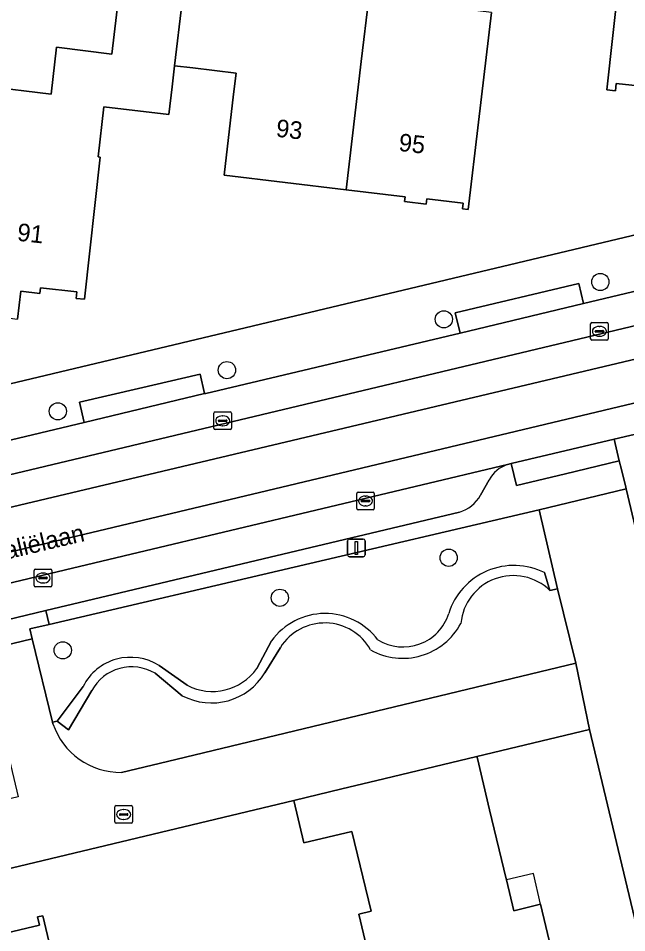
# Model space of a CAD drawing. Extents: x 162082 to 163401, y 388089 to 388636.
# Drawn here: x 163067.2 to 163101.7, y 388260.7 to 388312.7 of the extents above; entities that cross this region are included whole.
import ezdxf

# ---------------------------------------------------------------- set-up
doc = ezdxf.new("R2010")
doc.units = 0
for name, color, linetype in [('IMGEO_Boom', 7, 'Continuous'), ('IMGEO_Brandkraan', 7, 'Continuous'), ('IMGEO_Erf', 7, 'Continuous'), ('IMGEO_Fietspad_gesloten', 7, 'Continuous'), ('IMGEO_Groenvoorziening', 7, 'Continuous'), ('IMGEO_Haag', 7, 'Continuous'), ('IMGEO_Kolk', 7, 'Continuous'), ('IMGEO_Lichtmast', 7, 'Continuous'), ('IMGEO_Openbare_ruimte_label', 7, 'Continuous'), ('IMGEO_Pand', 7, 'Continuous'), ('IMGEO_Pand_nummerreeks', 7, 'Continuous'), ('IMGEO_Pand_overbouw', 7, 'Continuous'), ('IMGEO_Parkeervlak_gesloten', 7, 'Continuous'), ('IMGEO_Parkeervlak_open', 7, 'Continuous'), ('IMGEO_Rijbaan_lokaal_gesloten', 7, 'Continuous'), ('IMGEO_Voetpad_open', 7, 'Continuous')]:
    doc.layers.add(name, color=color, linetype=linetype)

msp = doc.modelspace()

# ---------------------------------------------------------------- linework, layer by layer
at = {"layer": 'IMGEO_Boom'}
for centre in [(163100.245, 388297.676), (163091.355, 388295.554), (163079.031, 388292.669), (163069.424, 388290.33), (163091.633, 388282.013), (163082.039, 388279.738), (163069.703, 388276.756)]:
    msp.add_circle(centre, 0.489, dxfattribs=at)
at = {"layer": 'IMGEO_Brandkraan'}
for p, q in [((163072.74, 388267.933), (163073.592, 388267.933)), ((163072.665, 388267.007), (163072.665, 388267.859)), ((163072.924, 388267.427), (163072.924, 388267.439)), ((163073.362, 388267.39), (163072.964, 388267.39)), ((163072.967, 388267.476), (163073.365, 388267.476)), ((163073.153, 388267.713), (163073.178, 388267.713)), ((163073.408, 388267.439), (163073.408, 388267.427)), ((163073.666, 388267.859), (163073.666, 388267.007)), ((163073.592, 388266.933), (163072.74, 388266.933)), ((163073.176, 388267.153), (163073.151, 388267.153))]:
    msp.add_line(p, q, dxfattribs=at)
for points in [[(163072.74, 388267.933), (163073.592, 388267.933)], [(163072.665, 388267.007), (163072.665, 388267.859)], [(163073.666, 388267.859), (163073.666, 388267.007)], [(163073.592, 388266.933), (163072.74, 388266.933)]]:
    msp.add_lwpolyline(points, dxfattribs=at)
for centre, radius, start, end in [((163072.742, 388267.857), 0.0765, 91.552, 178.448), ((163072.742, 388267.857), 0.0765, 91.552, 178.448), ((163073.59, 388267.857), 0.0765, 1.552, 88.448), ((163073.59, 388267.857), 0.0765, 1.552, 88.448), ((163072.964, 388267.436), 0.0403, 85.8775, 175.7526), ((163072.961, 388267.426), 0.0366, 178.938, 274.7102), ((163073.365, 388267.433), 0.043, 264.8664, 352.4533), ((163073.369, 388267.438), 0.0386, 1.7309, 96.639), ((163072.742, 388267.009), 0.0765, 181.552, 268.448), ((163072.742, 388267.009), 0.0765, 181.552, 268.448), ((163073.59, 388267.009), 0.0765, 271.552, 358.448), ((163073.59, 388267.009), 0.0765, 271.552, 358.448)]:
    msp.add_arc(centre, radius, start, end, dxfattribs=at)
for centre, major_axis, ratio, start_param, end_param in [((163073.152, 388267.433), (-0.387, 0.002), 0.722429, 4.712389, 7.853982), ((163073.177, 388267.433), (-0.39, 0.002), 0.717154, 1.570796, 4.712389)]:
    msp.add_ellipse(centre, major_axis=major_axis, ratio=ratio, start_param=start_param, end_param=end_param, dxfattribs=at)
at = {"layer": 'IMGEO_Erf'}
for points in [[(163013.441, 388370.076), (163002.97, 388276.7), (163142.597, 388309.979)], [(163115.606, 388318.173), (163114.904, 388310.765), (163115.585, 388310.468), (163115.233, 388307.247), (163114.536, 388307.323), (163114.509, 388307.074), (163114.127, 388307.119), (163114.177, 388307.482), (163111.934, 388307.715), (163111.899, 388307.38), (163110.705, 388307.504), (163110.765, 388307.946), (163107.613, 388308.272), (163101.145, 388308.941), (163101.103, 388308.536), (163100.622, 388308.594), (163101.28, 388314.604)], [(163065.297, 388308.795), (163069.042, 388308.351), (163069.356, 388311.006), (163072.487, 388310.619), (163073.322, 388317.664)], [(163094.057, 388312.987), (163093.32, 388306.76), (163092.732, 388301.794), (163092.421, 388301.831), (163092.46, 388302.161), (163090.397, 388302.405), (163090.36, 388302.097), (163089.126, 388302.243), (163089.158, 388302.514), (163085.798, 388302.912), (163078.866, 388303.733), (163079.413, 388308.351), (163079.555, 388309.542), (163077.085, 388309.835), (163076.059, 388309.956), (163075.918, 388308.765), (163075.731, 388307.184), (163072.033, 388307.622), (163071.721, 388304.785), (163071.83, 388304.772), (163070.94, 388296.69), (163070.468, 388296.746), (163070.51, 388297.107), (163068.444, 388297.351), (163068.405, 388297.018), (163067.313, 388297.148), (163067.132, 388295.572)], [(163104.946, 388250), (163099.632, 388272.251), (163093.238, 388270.721), (163093.262, 388270.617), (163093.959, 388267.699), (163094.894, 388263.781), (163094.91, 388263.713), (163095.326, 388261.968), (163096.857, 388262.333), (163097.97, 388257.667)], [(163087.681, 388256.901), (163086.52, 388261.764), (163087.221, 388261.933), (163086.135, 388266.466), (163083.409, 388265.815), (163082.833, 388268.229), (163042.708, 388258.625)], [(163062.455, 388259.741), (163068.38, 388261.15), (163068.27, 388261.61), (163068.57, 388261.682), (163069.727, 388256.818)]]:
    msp.add_lwpolyline(points, dxfattribs=at)
at = {"layer": 'IMGEO_Fietspad_gesloten'}
msp.add_lwpolyline([(163141.609, 388300.211), (163043.88, 388276.901), (163044.264, 388275.221), (163044.446, 388275.265), (163073.982, 388282.31), (163094.971, 388287.303), (163095.188, 388287.358), (163101.035, 388288.756), (163105.165, 388289.714), (163125.159, 388294.458), (163144.167, 388298.989)], dxfattribs=at)
at = {"layer": 'IMGEO_Groenvoorziening'}
for points in [[(163144.167, 388298.989), (163125.159, 388294.458), (163105.165, 388289.714), (163101.035, 388288.756), (163101.326, 388287.516), (163101.447, 388287.03), (163101.699, 388286.014), (163101.722, 388285.92), (163104.22, 388275.387), (163109.023, 388276.29), (163116.318, 388277.341), (163140.117, 388282.815), (163148.878, 388286.141), (163154.106, 388288.897), (163157.745, 388291.047), (163162.972, 388293.762)], [(163097.078, 388281.166), (163097.383, 388280.153), (163097.816, 388280.256), (163096.766, 388284.725), (163068.938, 388278.231), (163067.825, 388277.972), (163067.968, 388277.415), (163069.127, 388272.668), (163069.376, 388272.731), (163070.856, 388274.702)], [(163097.383, 388280.153), (163097.078, 388281.166)], [(163073.04, 388269.824), (163075.653, 388270.439), (163098.858, 388276.026), (163097.816, 388280.256)], [(163097.816, 388280.256), (163097.383, 388280.153)], [(163081.567, 388277.297), (163080.727, 388275.725)], [(163080.727, 388275.725), (163081.567, 388277.297)], [(163082.068, 388276.92), (163081.189, 388275.474)], [(163081.189, 388275.474), (163082.068, 388276.92)], [(163076.77, 388274.775), (163075.174, 388275.885)], [(163075.174, 388275.885), (163076.77, 388274.775)], [(163076.497, 388274.177), (163074.945, 388275.451)], [(163074.945, 388275.451), (163076.497, 388274.177)], [(163070.856, 388274.702), (163069.376, 388272.731), (163070.035, 388272.233), (163071.351, 388274.466)], [(163071.351, 388274.466), (163070.035, 388272.233), (163069.376, 388272.731), (163069.127, 388272.668), (163069.147, 388272.584)]]:
    msp.add_lwpolyline(points, dxfattribs=at)
for centre, radius, start, end in [((163095.342, 388277.695), 3.881, 63.4221, 162.8302), ((163095.342, 388277.695), 3.881, 63.4221, 162.8302), ((163095.3, 388278.007), 2.991, 45.8549, 174.6231), ((163095.3, 388278.007), 2.991, 45.8549, 174.6231), ((163084.608, 388275.087), 3.759, 36.9161, 143.9936), ((163084.608, 388275.087), 3.759, 36.9161, 143.9936), ((163089.036, 388279.673), 2.728, 238.5726, 342.2425), ((163089.036, 388279.673), 2.728, 238.5726, 342.2425), ((163084.588, 388275.328), 2.981, 29.097, 147.7058), ((163084.588, 388275.328), 2.981, 29.097, 147.7058), ((163089.016, 388280.051), 3.748, 240.8833, 331.92), ((163089.016, 388280.051), 3.748, 240.8833, 331.92), ((163073.549, 388273.344), 3.016, 57.3974, 153.2453), ((163073.549, 388273.344), 3.016, 57.3974, 153.2453), ((163073.616, 388273.251), 2.57, 58.8624, 151.7908), ((163073.616, 388273.251), 2.57, 58.8624, 151.7908), ((163078.208, 388277.5), 3.082, 242.1773, 324.823), ((163078.208, 388277.5), 3.082, 242.1773, 324.823), ((163078.153, 388277.321), 3.554, 242.2241, 328.6805), ((163078.153, 388277.321), 3.554, 242.2241, 328.6805), ((163072.986, 388273.874), 4.05, 198.5691, 270.7603)]:
    msp.add_arc(centre, radius, start, end, dxfattribs=at)
at = {"layer": 'IMGEO_Haag'}
for points in [[(163097.383, 388280.153), (163097.078, 388281.166)], [(163081.567, 388277.297), (163080.727, 388275.725)], [(163081.189, 388275.474), (163082.068, 388276.92)], [(163076.77, 388274.775), (163075.174, 388275.885)], [(163074.945, 388275.451), (163076.497, 388274.177)], [(163070.856, 388274.702), (163069.376, 388272.731), (163070.035, 388272.233), (163071.351, 388274.466)]]:
    msp.add_lwpolyline(points, dxfattribs=at)
for centre, radius, start, end in [((163095.342, 388277.695), 3.881, 63.4221, 162.8302), ((163095.3, 388278.007), 2.991, 45.8549, 174.6231), ((163084.608, 388275.087), 3.759, 36.9161, 143.9936), ((163089.036, 388279.673), 2.728, 238.5726, 342.2425), ((163084.588, 388275.328), 2.981, 29.097, 147.7058), ((163089.016, 388280.051), 3.748, 240.8833, 331.92), ((163073.549, 388273.344), 3.016, 57.3974, 153.2453), ((163073.616, 388273.251), 2.57, 58.8624, 151.7908), ((163078.208, 388277.5), 3.082, 242.1773, 324.823), ((163078.153, 388277.321), 3.554, 242.2241, 328.6805)]:
    msp.add_arc(centre, radius, start, end, dxfattribs=at)
at = {"layer": 'IMGEO_Kolk'}
for p, q in [((163099.697, 388294.449), (163099.697, 388295.301)), ((163099.772, 388295.375), (163100.624, 388295.375)), ((163099.999, 388294.918), (163100.397, 388294.918)), ((163100.185, 388295.155), (163100.21, 388295.155)), ((163100.698, 388295.301), (163100.698, 388294.449)), ((163099.956, 388294.869), (163099.956, 388294.881)), ((163100.394, 388294.832), (163099.996, 388294.832)), ((163100.208, 388294.595), (163100.183, 388294.595)), ((163100.44, 388294.881), (163100.44, 388294.869)), ((163100.624, 388294.375), (163099.772, 388294.375)), ((163078.367, 388290.293), (163079.219, 388290.293)), ((163078.292, 388289.367), (163078.292, 388290.219)), ((163078.551, 388289.787), (163078.551, 388289.799)), ((163078.989, 388289.75), (163078.591, 388289.75)), ((163078.594, 388289.836), (163078.992, 388289.836)), ((163078.78, 388290.073), (163078.805, 388290.073)), ((163079.035, 388289.799), (163079.035, 388289.787)), ((163079.293, 388290.219), (163079.293, 388289.367)), ((163079.219, 388289.293), (163078.367, 388289.293)), ((163078.803, 388289.513), (163078.778, 388289.513)), ((163086.404, 388284.808), (163086.404, 388285.66)), ((163086.479, 388285.734), (163087.331, 388285.734)), ((163087.405, 388285.66), (163087.405, 388284.808)), ((163086.663, 388285.228), (163086.663, 388285.24)), ((163087.101, 388285.191), (163086.703, 388285.191)), ((163086.706, 388285.277), (163087.104, 388285.277)), ((163086.892, 388285.514), (163086.917, 388285.514)), ((163087.147, 388285.24), (163087.147, 388285.228)), ((163087.331, 388284.734), (163086.479, 388284.734)), ((163086.915, 388284.954), (163086.89, 388284.954)), ((163068.081, 388280.433), (163068.081, 388281.285)), ((163068.156, 388281.359), (163069.008, 388281.359)), ((163068.383, 388280.902), (163068.781, 388280.902)), ((163068.569, 388281.139), (163068.594, 388281.139)), ((163069.082, 388281.285), (163069.082, 388280.433)), ((163069.008, 388280.359), (163068.156, 388280.359)), ((163068.34, 388280.853), (163068.34, 388280.865)), ((163068.778, 388280.816), (163068.38, 388280.816)), ((163068.592, 388280.579), (163068.567, 388280.579)), ((163068.824, 388280.865), (163068.824, 388280.853))]:
    msp.add_line(p, q, dxfattribs=at)
for points in [[(163099.697, 388294.449), (163099.697, 388295.301)], [(163099.772, 388295.375), (163100.624, 388295.375)], [(163100.698, 388295.301), (163100.698, 388294.449)], [(163100.624, 388294.375), (163099.772, 388294.375)], [(163078.367, 388290.293), (163079.219, 388290.293)], [(163078.292, 388289.367), (163078.292, 388290.219)], [(163079.293, 388290.219), (163079.293, 388289.367)], [(163079.219, 388289.293), (163078.367, 388289.293)], [(163086.404, 388284.808), (163086.404, 388285.66)], [(163086.479, 388285.734), (163087.331, 388285.734)], [(163087.405, 388285.66), (163087.405, 388284.808)], [(163087.331, 388284.734), (163086.479, 388284.734)], [(163068.081, 388280.433), (163068.081, 388281.285)], [(163068.156, 388281.359), (163069.008, 388281.359)], [(163069.082, 388281.285), (163069.082, 388280.433)], [(163069.008, 388280.359), (163068.156, 388280.359)]]:
    msp.add_lwpolyline(points, dxfattribs=at)
for centre, radius, start, end in [((163099.774, 388295.299), 0.0765, 91.552, 178.448), ((163099.774, 388295.299), 0.0765, 91.552, 178.448), ((163099.996, 388294.878), 0.0403, 85.8775, 175.7526), ((163100.401, 388294.88), 0.0386, 1.7309, 96.639), ((163100.622, 388295.299), 0.0765, 1.552, 88.448), ((163100.622, 388295.299), 0.0765, 1.552, 88.448), ((163099.774, 388294.451), 0.0765, 181.552, 268.448), ((163099.774, 388294.451), 0.0765, 181.552, 268.448), ((163099.993, 388294.868), 0.0366, 178.938, 274.7102), ((163100.397, 388294.875), 0.043, 264.8664, 352.4533), ((163100.622, 388294.451), 0.0765, 271.552, 358.448), ((163100.622, 388294.451), 0.0765, 271.552, 358.448), ((163078.369, 388290.217), 0.0765, 91.552, 178.448), ((163078.369, 388290.217), 0.0765, 91.552, 178.448), ((163079.217, 388290.217), 0.0765, 1.552, 88.448), ((163079.217, 388290.217), 0.0765, 1.552, 88.448), ((163078.591, 388289.796), 0.0403, 85.8775, 175.7526), ((163078.588, 388289.786), 0.0366, 178.938, 274.7102), ((163078.992, 388289.793), 0.043, 264.8664, 352.4533), ((163078.996, 388289.798), 0.0386, 1.7309, 96.639), ((163078.369, 388289.369), 0.0765, 181.552, 268.448), ((163078.369, 388289.369), 0.0765, 181.552, 268.448), ((163079.217, 388289.369), 0.0765, 271.552, 358.448), ((163079.217, 388289.369), 0.0765, 271.552, 358.448), ((163086.481, 388285.658), 0.0765, 91.552, 178.448), ((163086.481, 388285.658), 0.0765, 91.552, 178.448), ((163087.329, 388285.658), 0.0765, 1.552, 88.448), ((163087.329, 388285.658), 0.0765, 1.552, 88.448), ((163086.703, 388285.237), 0.0403, 85.8775, 175.7526), ((163086.7, 388285.227), 0.0366, 178.938, 274.7102), ((163087.104, 388285.234), 0.043, 264.8664, 352.4533), ((163087.108, 388285.239), 0.0386, 1.7309, 96.639), ((163086.481, 388284.81), 0.0765, 181.552, 268.448), ((163086.481, 388284.81), 0.0765, 181.552, 268.448), ((163087.329, 388284.81), 0.0765, 271.552, 358.448), ((163087.329, 388284.81), 0.0765, 271.552, 358.448), ((163068.158, 388281.283), 0.0765, 91.552, 178.448), ((163068.158, 388281.283), 0.0765, 91.552, 178.448), ((163068.38, 388280.862), 0.0403, 85.8775, 175.7526), ((163068.785, 388280.864), 0.0386, 1.7309, 96.639), ((163069.006, 388281.283), 0.0765, 1.552, 88.448), ((163069.006, 388281.283), 0.0765, 1.552, 88.448), ((163068.158, 388280.435), 0.0765, 181.552, 268.448), ((163068.158, 388280.435), 0.0765, 181.552, 268.448), ((163068.377, 388280.852), 0.0366, 178.938, 274.7102), ((163068.781, 388280.859), 0.043, 264.8664, 352.4533), ((163069.006, 388280.435), 0.0765, 271.552, 358.448), ((163069.006, 388280.435), 0.0765, 271.552, 358.448)]:
    msp.add_arc(centre, radius, start, end, dxfattribs=at)
for centre, major_axis, ratio, start_param, end_param in [((163100.184, 388294.875), (-0.387, 0.002), 0.722429, 4.712389, 7.853982), ((163100.209, 388294.875), (-0.39, 0.002), 0.717154, 1.570796, 4.712389), ((163078.779, 388289.793), (-0.387, 0.002), 0.722429, 4.712389, 7.853982), ((163078.804, 388289.793), (-0.39, 0.002), 0.717154, 1.570796, 4.712389), ((163086.891, 388285.234), (-0.387, 0.002), 0.722429, 4.712389, 7.853982), ((163086.916, 388285.234), (-0.39, 0.002), 0.717154, 1.570796, 4.712389), ((163068.568, 388280.859), (-0.387, 0.002), 0.722429, 4.712389, 7.853982), ((163068.593, 388280.859), (-0.39, 0.002), 0.717154, 1.570796, 4.712389)]:
    msp.add_ellipse(centre, major_axis=major_axis, ratio=ratio, start_param=start_param, end_param=end_param, dxfattribs=at)
at = {"layer": 'IMGEO_Lichtmast'}
for p, q in [((163085.888, 388282.17), (163085.888, 388282.97)), ((163085.888, 388282.97), (163085.888, 388282.17)), ((163085.988, 388283.07), (163086.778, 388283.07)), ((163086.778, 388283.07), (163085.988, 388283.07)), ((163086.878, 388282.97), (163086.878, 388282.17)), ((163086.878, 388282.17), (163086.878, 388282.97)), ((163086.778, 388282.07), (163085.988, 388282.07)), ((163085.988, 388282.07), (163086.778, 388282.07))]:
    msp.add_line(p, q, dxfattribs=at)
msp.add_lwpolyline([(163086.308, 388282.945), (163086.458, 388282.945), (163086.458, 388282.195), (163086.308, 388282.195), (163086.308, 388282.945)], dxfattribs=at)
for centre, start, end in [((163085.988, 388282.97), 90, 180), ((163085.988, 388282.97), 90, 180), ((163086.778, 388282.97), 0, 90), ((163086.778, 388282.97), 360, 90), ((163085.988, 388282.17), 180, 270), ((163085.988, 388282.17), 180, 270), ((163086.778, 388282.17), 270, 0), ((163086.778, 388282.17), 270, 0)]:
    msp.add_arc(centre, 0.1, start, end, dxfattribs=at)
at = {"layer": 'IMGEO_Pand'}
for points in [[(163087.265, 388315.326), (163082.654, 388315.871), (163082.101, 388315.936), (163081.729, 388325.095), (163078.179, 388325.515), (163077.861, 388325.553), (163077.744, 388325.567), (163077.12, 388320.084), (163077.257, 388320.069), (163077.171, 388319.345), (163076.922, 388317.238), (163076.059, 388309.956), (163077.085, 388309.835), (163079.555, 388309.542), (163079.413, 388308.351), (163078.866, 388303.733), (163085.798, 388302.912), (163086.66, 388310.206), (163087.086, 388313.811)], [(163108.652, 388319.062), (163108.754, 388320.017), (163102.201, 388320.717), (163102.482, 388323.342), (163100.234, 388323.582), (163099.025, 388323.711), (163098.895, 388322.528), (163098.065, 388314.956), (163101.28, 388314.604), (163100.622, 388308.594), (163101.103, 388308.536), (163101.145, 388308.941), (163107.613, 388308.272)], [(163071.83, 388304.772), (163071.721, 388304.785), (163072.033, 388307.622), (163075.731, 388307.184), (163075.918, 388308.765), (163076.059, 388309.956), (163076.922, 388317.238), (163073.322, 388317.664), (163072.487, 388310.619), (163069.356, 388311.006), (163069.042, 388308.351), (163065.297, 388308.795), (163064.027, 388297.798), (163063.818, 388295.992), (163067.132, 388295.572), (163067.313, 388297.148), (163068.405, 388297.018), (163068.444, 388297.351), (163070.51, 388297.107), (163070.468, 388296.746), (163070.94, 388296.69)], [(163094.057, 388312.987), (163090.793, 388313.373), (163087.086, 388313.811), (163086.66, 388310.206), (163085.798, 388302.912), (163089.158, 388302.514), (163089.126, 388302.243), (163090.36, 388302.097), (163090.397, 388302.405), (163092.46, 388302.161), (163092.421, 388301.831), (163092.732, 388301.794), (163093.32, 388306.76)], [(163094.894, 388263.781), (163093.959, 388267.699), (163093.262, 388270.617), (163093.238, 388270.721), (163087.938, 388269.453), (163085.556, 388268.882), (163082.833, 388268.229), (163083.409, 388265.815), (163086.135, 388266.466), (163087.221, 388261.933), (163086.52, 388261.764), (163087.681, 388256.901), (163088.068, 388255.278), (163088.861, 388255.467), (163096.398, 388257.292), (163097.97, 388257.667), (163096.857, 388262.333), (163095.326, 388261.968), (163094.91, 388263.713)], [(163062.13, 388260.195), (163064.27, 388251.186), (163067.689, 388252), (163068.165, 388250), (163068.514, 388248.53), (163071.527, 388249.247), (163071.348, 388250), (163069.727, 388256.818), (163068.57, 388261.682), (163068.27, 388261.61), (163068.38, 388261.15), (163062.455, 388259.741), (163062.335, 388260.244)]]:
    msp.add_lwpolyline(points, close=True, dxfattribs=at)
at = {"layer": 'IMGEO_Pand_overbouw'}
msp.add_lwpolyline([(163096.441, 388264.078), (163094.91, 388263.713), (163095.326, 388261.968), (163096.857, 388262.333)], close=True, dxfattribs=at)
at = {"layer": 'IMGEO_Parkeervlak_gesloten'}
for points in [[(163094.971, 388287.303), (163073.982, 388282.31), (163044.446, 388275.265)], [(163093.442, 388285.562), (163093.931, 388286.437)], [(163047.26, 388273.86), (163063.848, 388277.845), (163068.744, 388279.022), (163092.24, 388284.602)]]:
    msp.add_lwpolyline(points, dxfattribs=at)
for centre, radius, start, end in [((163095.519, 388285.588), 1.801, 107.7118, 151.856), ((163091.624, 388286.606), 2.097, 287.0911, 330.1354)]:
    msp.add_arc(centre, radius, start, end, dxfattribs=at)
at = {"layer": 'IMGEO_Parkeervlak_open'}
msp.add_lwpolyline([(163131.452, 388304.096), (163121.683, 388301.766), (163118.841, 388301.096), (163113.942, 388299.941), (163113.922, 388299.936), (163099.299, 388296.452), (163092.277, 388294.775), (163077.825, 388291.351), (163077.761, 388291.336), (163070.915, 388289.699), (163056.768, 388286.318), (163048.255, 388284.284), (163041.524, 388282.675), (163034.48, 388280.986), (163034.6, 388280.484), (163034.915, 388279.158), (163042.673, 388281.006), (163042.839, 388281.046), (163134.34, 388302.847)], dxfattribs=at)
at = {"layer": 'IMGEO_Rijbaan_lokaal_gesloten'}
for points in [[(163142.688, 388304.634), (163140.488, 388304.158), (163140.267, 388304.121), (163137.957, 388303.61), (163135.31, 388303.025), (163134.34, 388302.847), (163042.839, 388281.046), (163043.268, 388279.323), (163142.15, 388302.761)], [(163142.15, 388302.761), (163043.268, 388279.323), (163042.839, 388281.046), (163042.673, 388281.006), (163044.074, 388275.176), (163044.264, 388275.221), (163043.88, 388276.901), (163141.609, 388300.211)]]:
    msp.add_lwpolyline(points, dxfattribs=at)
at = {"layer": 'IMGEO_Voetpad_open'}
for points in [[(163142.597, 388309.979), (163002.97, 388276.7), (162998.906, 388275.686), (162998.667, 388273.56), (162969.954, 388266.671), (162969.935, 388266.571), (162965.617, 388265.468)], [(163048.255, 388284.284), (163047.905, 388285.749), (163051.827, 388286.683), (163056.421, 388287.778), (163056.768, 388286.318), (163070.915, 388289.699), (163070.647, 388290.851), (163073.998, 388291.632), (163077.501, 388292.448), (163077.761, 388291.336), (163077.825, 388291.351), (163092.277, 388294.775), (163092.006, 388295.914), (163099.028, 388297.588), (163099.299, 388296.452), (163113.922, 388299.936), (163113.655, 388301.048), (163121.409, 388302.909), (163121.683, 388301.766), (163131.452, 388304.096)], [(163101.722, 388285.92), (163101.699, 388286.014), (163101.447, 388287.03), (163101.326, 388287.516), (163098.266, 388286.781), (163095.486, 388286.113), (163095.188, 388287.358), (163094.971, 388287.303)], [(163093.931, 388286.437), (163093.442, 388285.562)], [(163092.24, 388284.602), (163068.744, 388279.022), (163068.938, 388278.231), (163096.766, 388284.725), (163101.722, 388285.92)], [(163069.147, 388272.584), (163069.127, 388272.668), (163067.968, 388277.415), (163065.198, 388276.749), (163066.421, 388271.593), (163066.582, 388270.914), (163067.169, 388268.441), (163042.016, 388262.421), (163041.18, 388265.957), (163040.358, 388269.435)], [(163082.833, 388268.229), (163085.556, 388268.882), (163087.938, 388269.453), (163093.238, 388270.721), (163099.632, 388272.251), (163098.858, 388276.026), (163075.653, 388270.439), (163073.04, 388269.824)], [(163037.705, 388267.654), (163037.741, 388267.499), (163037.952, 388266.575), (163038.045, 388266.167), (163038.988, 388262.079), (163039.484, 388260.157), (163039.991, 388257.973), (163042.708, 388258.625), (163082.833, 388268.229)]]:
    msp.add_lwpolyline(points, dxfattribs=at)
for points in [[(163099.299, 388296.452), (163099.028, 388297.588), (163092.006, 388295.914), (163092.277, 388294.775)], [(163077.761, 388291.336), (163077.501, 388292.448), (163073.998, 388291.632), (163070.647, 388290.851), (163070.915, 388289.699)], [(163101.326, 388287.516), (163101.035, 388288.756), (163095.188, 388287.358), (163095.486, 388286.113), (163098.266, 388286.781)], [(163101.722, 388285.92), (163096.766, 388284.725), (163097.816, 388280.256), (163098.858, 388276.026), (163099.632, 388272.251), (163104.946, 388250), (163115.065, 388207.627), (163120.01, 388208.904), (163110.246, 388249.871), (163104.398, 388274.613), (163104.22, 388275.387)], [(163068.938, 388278.231), (163068.744, 388279.022), (163063.848, 388277.845), (163064.037, 388277.065), (163065.059, 388277.308), (163065.198, 388276.749), (163067.968, 388277.415), (163067.825, 388277.972)]]:
    msp.add_lwpolyline(points, close=True, dxfattribs=at)
for centre, radius, start, end in [((163095.519, 388285.588), 1.801, 107.7118, 151.856), ((163091.624, 388286.606), 2.097, 287.0911, 330.1354), ((163072.986, 388273.874), 4.05, 198.5691, 270.7603)]:
    msp.add_arc(centre, radius, start, end, dxfattribs=at)

# ---------------------------------------------------------------- texts
at = {"layer": 'IMGEO_Openbare_ruimte_label'}
msp.add_text('Italiëlaan', height=1, rotation=13.2996, dxfattribs=at).set_placement((163065.797, 388281.742))
at = {"layer": 'IMGEO_Pand_nummerreeks'}
for s, rotation, p in [('93', 353.3995, (163081.785, 388305.933)), ('95', 353.3995, (163088.755, 388305.126)), ('91', 353.56, (163067.08, 388300.027))]:
    msp.add_text(s, height=1, rotation=rotation, dxfattribs=at).set_placement(p)

doc.saveas('drawing.dxf')
